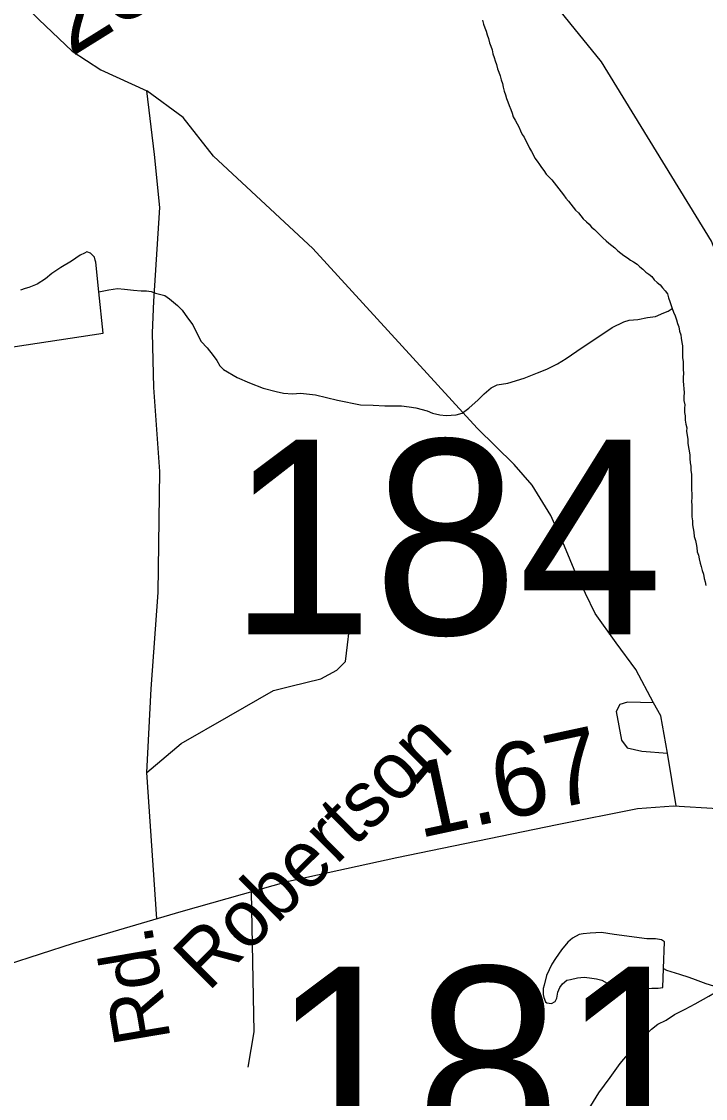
# Model space of a CAD drawing. Extents: x 2001466 to 31450019, y -30647475 to 847247.
# Drawn here: x 2171092 to 2173396, y 751813 to 755442 of the extents above; entities that cross this region are included whole.
import ezdxf

# ---------------------------------------------------------------- set-up
doc = ezdxf.new("R2010")
doc.units = 0
for name, color, linetype in [('Exist Hydrographic Creek Single Shore', 7, 'Continuous'), ('Exist Hydrographic Misc Water Feature', 7, 'Continuous'), ('Exist Road Non-System Type 51', 7, 'Continuous'), ('Exist Road Secondary Mileage Hundredths English Label', 7, 'Continuous'), ('Exist Road Secondary Structure Standard Bridge Number Label', 7, 'Continuous'), ('Exist Road Secondary Type 41 Attributed', 7, 'Continuous'), ('Exist Road Secondary Type 51 Attributed', 7, 'Continuous'), ('Exist Road Secondary Type 51 Label', 7, 'Continuous'), ('Exist Road Secondary Type 51 Number Label', 7, 'Continuous')]:
    doc.layers.add(name, color=color, linetype=linetype)

msp = doc.modelspace()

# ---------------------------------------------------------------- linework, layer by layer
at = {"layer": 'Exist Hydrographic Creek Single Shore'}
msp.add_lwpolyline([(2173972, 753669.7), (2173922, 753687.2), (2173551.1, 754350.8), (2173416.1, 754701.4), (2173046, 755306), (2172711.2, 755719.6), (2172166.1, 756275.3), (2172090.1, 756418), (2171988.1, 756817), (2171802.2, 757283.4), (2171727.1, 757380.1), (2171592.2, 757687.9), (2171415, 757986.8), (2171356.2, 758155.3), (2171285, 758888.3), (2171166.1, 759353.3)], dxfattribs=at)
at = {"layer": 'Exist Hydrographic Misc Water Feature'}
for points in [[(2172645.3, 755446.1), (2172648.8, 755432.2), (2172653.3, 755420.2), (2172657.2, 755408.6), (2172661.1, 755396.3), (2172665.6, 755384.2), (2172669.1, 755370.3), (2172673.6, 755358.3), (2172677.5, 755346.7), (2172679.6, 755332.7), (2172683.9, 755320.6), (2172687.8, 755308.7), (2172691.7, 755296.7), (2172695.8, 755282.7), (2172700.3, 755270.7), (2172704.2, 755258.8), (2172708.3, 755244.8), (2172712.6, 755232.7), (2172714.4, 755220.7), (2172718.3, 755206.7), (2172722.4, 755194.7), (2172726.3, 755182.8), (2172730.6, 755170.7), (2172734.7, 755158.8), (2172740.9, 755144.9), (2172744.8, 755133), (2172748.7, 755121), (2172754.8, 755109.1), (2172761.4, 755097.2), (2172766.9, 755087), (2172773.1, 755073.1), (2172779.2, 755061.2), (2172785.2, 755051.4), (2172791.3, 755039.5), (2172797.3, 755027.2), (2172803.4, 755015.4), (2172809.6, 755003.5), (2172815.5, 754993.3), (2172821.7, 754981.4), (2172829.7, 754971.6), (2172837.5, 754959.5), (2172843.8, 754949.6), (2172852, 754939.4), (2172859.8, 754927.7), (2172870.1, 754917.6), (2172878.3, 754907.9), (2172885.9, 754897.8), (2172894.1, 754888.1), (2172902.1, 754877.9), (2172910.3, 754867.8), (2172918.3, 754858), (2172926.1, 754845.9), (2172934.3, 754836.1), (2172942.3, 754826), (2172950.5, 754816.3), (2172958.7, 754806.5), (2172968.5, 754796.5), (2172976.5, 754786.4), (2172984.7, 754776.2), (2172995, 754766.5), (2173004.6, 754758.6), (2173012.8, 754748.4), (2173022.8, 754740.8), (2173032.7, 754730.8), (2173042.9, 754720.7), (2173050.9, 754713.1), (2173061.2, 754703), (2173071, 754695), (2173081.1, 754687), (2173091.3, 754679), (2173101.4, 754668.9), (2173111.2, 754661.3), (2173121.5, 754653.3), (2173133.2, 754645.4), (2173143.4, 754637.4), (2173153.5, 754631.4), (2173165.8, 754623.5), (2173175.4, 754615.5), (2173185.7, 754607.5), (2173195.5, 754597.5), (2173205.5, 754589.9), (2173215.8, 754581.9), (2173223.8, 754571.7), (2173233.6, 754562.1), (2173243.9, 754554.1), (2173251.9, 754543.9), (2173260.1, 754534.2), (2173268.1, 754524.1), (2173272.2, 754510.1), (2173276.1, 754498.1), (2173284.1, 754474.2)], [(2171352.7, 754531.3), (2171342.2, 754631), (2171340.2, 754637), (2171337.9, 754647.1), (2171329.9, 754655.2), (2171323.8, 754661), (2171311.7, 754665.2), (2171303.9, 754661.2), (2171289.9, 754654.7), (2171259.8, 754634.6), (2171224.3, 754612.3), (2171194.2, 754592.5), (2171172.5, 754574.3), (2171144.4, 754556.3), (2171116.7, 754545.8), (2171104.6, 754542), (2171088.8, 754535.9)], [(2171352.7, 754531.3), (2171386.5, 754537.5), (2171414.8, 754541.7), (2171438.6, 754539.8), (2171468.8, 754536), (2171494.8, 754534.1), (2171512.6, 754534.3), (2171528.8, 754532.3), (2171542.8, 754526.5), (2171574.6, 754518.4), (2171590.4, 754506.7), (2171617, 754484.8), (2171632.6, 754469.1), (2171651.3, 754443.2), (2171668.9, 754419), (2171683.4, 754389.2), (2171697.4, 754363.1), (2171717.7, 754341.5), (2171737.6, 754315.7), (2171749.7, 754299.7), (2171759.9, 754281.5), (2171772, 754269.5), (2171818.4, 754241.8), (2171860, 754224.2), (2171906.3, 754206.6), (2171950.2, 754194.7), (2171974.4, 754189), (2172004.4, 754186.9), (2172032.2, 754189.2), (2172052.3, 754187.4), (2172082.3, 754183.7), (2172156.3, 754166), (2172234.4, 754150.5), (2172276.2, 754148.7), (2172316.4, 754147.1), (2172372.4, 754147.1), (2172398.1, 754143.2), (2172420.4, 754139.4), (2172458.3, 754129.6), (2172476.6, 754121.6), (2172500.8, 754115.9), (2172522.5, 754113.9), (2172556.4, 754116), (2172576.7, 754122.4), (2172598.4, 754138.5), (2172630.2, 754166.5), (2172650.3, 754186.6), (2172674.1, 754207), (2172693.9, 754217), (2172729.8, 754223.3), (2172785.6, 754239.6), (2172829.9, 754257.6), (2172861.7, 754269.9), (2172897.4, 754288), (2172927.1, 754306.2), (2172980.8, 754342.7), (2173013, 754364.7), (2173082.3, 754411), (2173120.7, 754429.1), (2173138.7, 754435.3), (2173168.8, 754437.6), (2173200.8, 754443.8), (2173228.3, 754448.1), (2173256.2, 754460.1), (2173270.3, 754466.1), (2173284.1, 754474.2)], [(2170719.5, 754413.6), (2170727.9, 754407.9), (2170739.6, 754402), (2170751.7, 754399.8), (2170765.6, 754400.1), (2170795.8, 754412.2), (2170811.6, 754420.4), (2170853.6, 754440.4), (2170873.5, 754442.7), (2170887.4, 754444.6), (2170913.3, 754436.6), (2170925.4, 754430.8), (2170937.3, 754424.9), (2170949.4, 754413), (2170965.6, 754403.2), (2170973.6, 754393.1), (2170979.9, 754387.2), (2170995.9, 754371.4), (2171011.7, 754351.6), (2171029.9, 754343.6), (2171033.8, 754341.3), (2171367.3, 754391.5), (2171352.7, 754531.3)], [(2173284.1, 754474.2), (2173288.4, 754462.1), (2173294.1, 754450.3), (2173298.6, 754436.3), (2173302.5, 754424.3), (2173306.4, 754412.3), (2173308.9, 754398.2), (2173312.8, 754386.3), (2173314.6, 754374.6), (2173317.1, 754360.5), (2173319.1, 754348.4), (2173319.1, 754334.6), (2173319.1, 754322.4), (2173318.9, 754308.6), (2173321.2, 754296.5), (2173321.4, 754282.3), (2173321.2, 754268.6), (2173321.8, 754256.3), (2173321.6, 754242.6), (2173321.6, 754230.4), (2173322, 754216.5), (2173323.7, 754204.5), (2173324.1, 754190.7), (2173323.7, 754178.5), (2173323.9, 754164.7), (2173326.3, 754150.5), (2173325.9, 754138.5), (2173326.1, 754124.6), (2173328.4, 754112.5), (2173328.2, 754098.8), (2173330.6, 754084.6), (2173332.9, 754072.5), (2173332.5, 754060.8), (2173334.5, 754046.7), (2173336.8, 754034.6), (2173337, 754020.8), (2173338.8, 754006.7), (2173341.1, 753994.6), (2173343.1, 753980.9), (2173343.1, 753968.7), (2173345, 753954.6), (2173347.4, 753942.9), (2173347.4, 753928.7), (2173349.3, 753916.7), (2173349.5, 753902.8), (2173349.3, 753890.7), (2173349.5, 753876.9), (2173349.3, 753862.7), (2173349.9, 753850.9), (2173350.1, 753836.7), (2173349.7, 753824.9), (2173349.9, 753810.7), (2173350.1, 753798.9), (2173349.9, 753784.7), (2173350.1, 753772.9), (2173352.4, 753758.8), (2173352.2, 753745.1), (2173354.4, 753733), (2173356.7, 753720.9), (2173358.5, 753706.8), (2173362.6, 753692.8), (2173364.9, 753681.1), (2173366.7, 753669), (2173368.6, 753654.9), (2173373.1, 753642.9), (2173375.3, 753630.8), (2173378.8, 753616.9), (2173381.3, 753605.2), (2173385.2, 753591.2), (2173389.3, 753579.2), (2173391.5, 753565.1), (2173395.4, 753553.1), (2173397.7, 753541)], [(2173254.8, 752250.8), (2173258.2, 752340.7), (2173248.6, 752346.6), (2173228.3, 752350.5), (2173198.2, 752350.6), (2173088.1, 752365.6), (2173046.2, 752371.5), (2173008.3, 752369.2), (2172984.3, 752367.1), (2172970.4, 752365.2), (2172948.4, 752353.1), (2172932.4, 752338.9), (2172910.7, 752312.9), (2172890.6, 752284.7), (2172878.7, 752264.6), (2172861.1, 752226.7), (2172853.1, 752194.7), (2172849.4, 752182.6), (2172849.6, 752170.5), (2172849.4, 752162.4), (2172851.6, 752152.3), (2172857.8, 752138.4), (2172861.9, 752134.5), (2172877.7, 752132.5), (2172889.8, 752138.8), (2172895.5, 752150.9), (2172899.2, 752170.6), (2172905.3, 752186.8), (2172915, 752198.7), (2172929.3, 752210.7), (2172941.2, 752213), (2172965, 752219.1), (2172987.2, 752221.1), (2173005.2, 752219.5), (2173029.2, 752215.5), (2173047.2, 752211.6), (2173065.1, 752201.6), (2173085, 752193.7), (2173109.4, 752181.9), (2173135.6, 752175.9), (2173173.4, 752176.3), (2173195.3, 752182.3), (2173215.2, 752184.5), (2173237.3, 752184.5), (2173252.9, 752186.9), (2173254.8, 752250.8)], [(2173254.8, 752250.8), (2173264.8, 752244.8), (2173308.9, 752231.2), (2173340.7, 752221.1), (2173361, 752213.2), (2173397.1, 752199.6), (2173422.9, 752191.7), (2173445.3, 752179.8)], [(2172896.5, 751584.9), (2172904.5, 751605.2), (2172912.3, 751621), (2172928.1, 751645), (2172946.2, 751681.3), (2172965.8, 751713.1), (2172991.9, 751759.5), (2173009.7, 751787.6), (2173037.4, 751831.7), (2173074.9, 751883.6), (2173108.6, 751930.1), (2173152.2, 751982.3), (2173184.2, 752016.4), (2173214, 752046.4), (2173235.7, 752063), (2173264, 752077), (2173291.7, 752095.1), (2173327.3, 752113.2), (2173361.4, 752131.2), (2173407.5, 752157.5), (2173445.3, 752179.8)]]:
    msp.add_lwpolyline(points, dxfattribs=at)
at = {"layer": 'Exist Road Non-System Type 51'}
for p, q in [((2173297.2, 752798.3), (2173268, 752976.2)), ((2171547.9, 752418.3), (2171513.9, 752911.2))]:
    msp.add_line(p, q, dxfattribs=at)
for points in [[(2173221.3, 753146.3), (2173161.8, 753258.3), (2173095.2, 753347.6), (2173024.3, 753446.9), (2172959.1, 753581.3), (2172920.9, 753673.4), (2172875.5, 753776.9), (2172811.8, 753879), (2172752, 753948.5), (2172627.3, 754071.8), (2172073.3, 754677.2), (2171738.1, 754987.4), (2171636.1, 755117.9), (2171513.9, 755207.8)], [(2171513.9, 752911.2), (2171528.4, 753192.5), (2171552.7, 753517.4), (2171557.5, 753924.8), (2171538.1, 754208.5), (2171533.3, 754392.8), (2171538.1, 754499.5), (2171557.5, 754814.8), (2171539.7, 754993.1), (2171513.9, 755207.8)], [(2171513.9, 752911.2), (2171630.2, 753008.2), (2171790.2, 753100.4), (2171940.5, 753187.7), (2171998.7, 753202.2), (2172100.5, 753226.4), (2172153.8, 753255.5), (2172182.9, 753284.6), (2172202.3, 753444.7)], [(2173221.3, 753146.3), (2173133.4, 753147.7), (2173107.9, 753140.6), (2173095.2, 753116.5), (2173113.6, 753020.1), (2173132, 752994.6), (2173181.6, 752983.2), (2173268, 752976.2)], [(2173268, 752976.2), (2173245.3, 753102.3), (2173221.3, 753146.3)], [(2171865.8, 752509.3), (2171874.1, 752036.7), (2171854.3, 751917.6)]]:
    msp.add_lwpolyline(points, dxfattribs=at)
at = {"layer": 'Exist Road Secondary Type 41 Attributed'}
msp.add_lwpolyline([(2168539.1, 756452.8), (2168805.9, 756432.9), (2169214, 756397.3), (2169592.8, 756365.9), (2169826.1, 756338.7), (2169974.7, 756307.3), (2170112.8, 756240.2), (2170361.9, 756074.8), (2170663.2, 755848.6), (2170888.2, 755685.3), (2170990.7, 755605.7), (2171149.8, 755448.6), (2171262.8, 755341.8), (2171359.1, 755279), (2171513.9, 755207.8)], dxfattribs=at)
at = {"layer": 'Exist Road Secondary Type 51 Attributed'}
msp.add_lwpolyline([(2169290.9, 752064.3), (2169365.2, 752080), (2169582.8, 752090.5), (2169949.1, 752107.3), (2170269.3, 752126.1), (2170490, 752140.8), (2170630.3, 752149.1), (2170755.8, 752170.1), (2171044.6, 752264.3), (2171266.5, 752335.5), (2171629.6, 752442.3), (2171991.6, 752545), (2172356.8, 752624.5), (2172896.7, 752735.5), (2173166.7, 752790), (2173288.1, 752798.4), (2173587.5, 752780.5), (2173854.3, 752762.2), (2174064.7, 752747.5)], dxfattribs=at)

# ---------------------------------------------------------------- texts
at = {"layer": 'Exist Road Secondary Mileage Hundredths English Label'}
msp.add_text('1.67', height=250, rotation=12.1429, dxfattribs=at).set_placement((2172431.5, 752689.2))
at = {"layer": 'Exist Road Secondary Structure Standard Bridge Number Label'}
for s, p in [('184', (2171789.3, 753376.3)), ('181', (2171932.1, 751600))]:
    msp.add_text(s, height=656.17, dxfattribs=at).set_placement(p)
at = {"layer": 'Exist Road Secondary Type 51 Label'}
for s, rotation, p in [('Robertson', 44.752, (2171720.8, 752169.5)), ('Rd.', 99.5568, (2171595.1, 752012.6))]:
    msp.add_text(s, height=190, rotation=rotation, dxfattribs=at).set_placement(p)
at = {"layer": 'Exist Road Secondary Type 51 Number Label'}
msp.add_text('2323', height=250, rotation=31.918, dxfattribs=at).set_placement((2171258.6, 755320.7))

doc.saveas('drawing.dxf')
